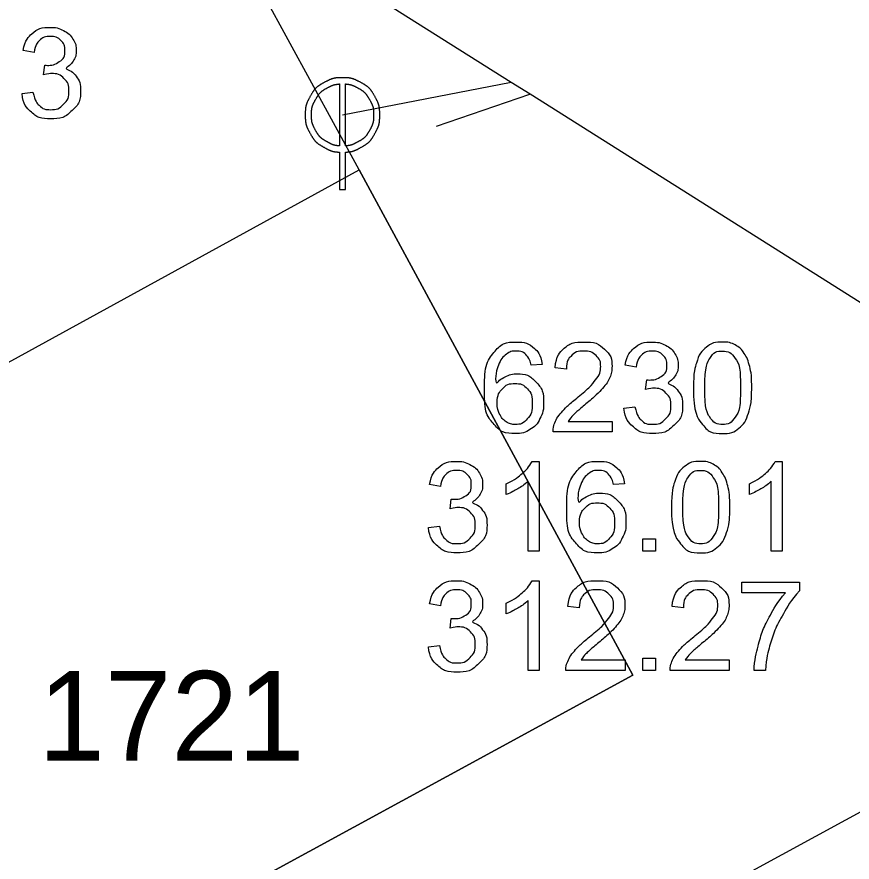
# Model space of a CAD drawing. Extents: x -562248 to -562040, y -1079385 to -1079027.
# Drawn here: x -562106.88 to -562092.87, y -1079267.68 to -1079253.52 of the extents above; entities that cross this region are included whole.
import ezdxf

# ---------------------------------------------------------------- set-up
doc = ezdxf.new("R2010")
doc.units = 0
for name, color, linetype in [('Default', 7, 'Continuous'), ('Kanalizační přípojka', 7, 'Continuous'), ('Kanalizační stoka', 7, 'Continuous'), ('Kanalizační šachta', 7, 'Continuous'), ('Parcela-polygon', 7, 'Continuous'), ('Parcela-text', 7, 'Continuous'), ('Popis šachty', 7, 'Continuous')]:
    doc.layers.add(name, color=color, linetype=linetype)

msp = doc.modelspace()

# ---------------------------------------------------------------- linework, layer by layer
at = {"layer": 'Default'}
for points in [[(-562101.42, -1079254.535), (-562101.526, -1079254.535), (-562101.628, -1079254.562), (-562101.728, -1079254.616)], [(-562101.112, -1079254.616), (-562101.212, -1079254.562), (-562101.314, -1079254.535), (-562101.42, -1079254.535)], [(-562101.728, -1079254.616), (-562101.827, -1079254.669), (-562101.905, -1079254.746), (-562101.961, -1079254.846)], [(-562101.87, -1079254.899), (-562101.824, -1079254.816), (-562101.759, -1079254.751), (-562101.676, -1079254.706)], [(-562101.676, -1079254.706), (-562101.605, -1079254.668), (-562101.536, -1079254.646), (-562101.471, -1079254.64)], [(-562101.369, -1079254.64), (-562101.302, -1079254.646), (-562101.234, -1079254.668), (-562101.164, -1079254.706)], [(-562101.164, -1079254.706), (-562101.081, -1079254.751), (-562101.016, -1079254.816), (-562100.968, -1079254.899)], [(-562100.879, -1079254.846), (-562100.935, -1079254.746), (-562101.013, -1079254.669), (-562101.112, -1079254.616)], [(-562101.961, -1079254.846), (-562102.017, -1079254.946), (-562102.045, -1079255.051), (-562102.045, -1079255.16)], [(-562100.795, -1079255.16), (-562100.795, -1079255.051), (-562100.823, -1079254.946), (-562100.879, -1079254.846)], [(-562101.94, -1079255.16), (-562101.94, -1079255.069), (-562101.917, -1079254.982), (-562101.87, -1079254.899)], [(-562100.968, -1079254.899), (-562100.921, -1079254.982), (-562100.898, -1079255.069), (-562100.898, -1079255.16)], [(-562102.045, -1079255.16), (-562102.045, -1079255.267), (-562102.017, -1079255.371), (-562101.962, -1079255.47)], [(-562101.872, -1079255.418), (-562101.917, -1079255.335), (-562101.94, -1079255.25), (-562101.94, -1079255.16)], [(-562100.898, -1079255.16), (-562100.898, -1079255.25), (-562100.92, -1079255.335), (-562100.966, -1079255.418)], [(-562100.877, -1079255.47), (-562100.822, -1079255.371), (-562100.795, -1079255.267), (-562100.795, -1079255.16)], [(-562101.679, -1079255.609), (-562101.762, -1079255.564), (-562101.826, -1079255.5), (-562101.872, -1079255.418)], [(-562100.966, -1079255.418), (-562101.011, -1079255.5), (-562101.076, -1079255.564), (-562101.159, -1079255.609)], [(-562101.962, -1079255.47), (-562101.907, -1079255.569), (-562101.829, -1079255.647), (-562101.73, -1079255.702)], [(-562101.108, -1079255.702), (-562101.008, -1079255.647), (-562100.931, -1079255.569), (-562100.877, -1079255.47)], [(-562101.73, -1079255.702), (-562101.644, -1079255.751), (-562101.558, -1079255.778), (-562101.471, -1079255.783)], [(-562101.471, -1079255.678), (-562101.54, -1079255.673), (-562101.609, -1079255.65), (-562101.679, -1079255.609)], [(-562101.159, -1079255.609), (-562101.23, -1079255.65), (-562101.3, -1079255.673), (-562101.369, -1079255.678)], [(-562101.369, -1079255.783), (-562101.282, -1079255.778), (-562101.195, -1079255.751), (-562101.108, -1079255.702)]]:
    msp.add_open_spline(points, degree=2, dxfattribs=at)
at = {"layer": 'Kanalizační přípojka'}
for points in [[(-562101.42, -1079255.16), (-562098.59, -1079254.61)], [(-562099.845, -1079255.35), (-562098.28, -1079254.81), (-562098.274, -1079254.808)]]:
    msp.add_lwpolyline(points, dxfattribs=at)
at = {"layer": 'Kanalizační stoka'}
msp.add_lwpolyline([(-562104.57, -1079250.84), (-562098.59, -1079254.61), (-562098.276, -1079254.807), (-562091.1, -1079259.33)], dxfattribs=at)
at = {"layer": 'Kanalizační šachta'}
for points in [[(-562101.471, -1079254.64), (-562101.471, -1079255.678)], [(-562101.369, -1079255.678), (-562101.369, -1079254.64)], [(-562101.471, -1079256.41), (-562101.369, -1079256.41), (-562101.369, -1079255.783)], [(-562101.471, -1079255.783), (-562101.471, -1079256.41)]]:
    msp.add_lwpolyline(points, dxfattribs=at)
at = {"layer": 'Parcela-polygon'}
for points in [[(-562125.839, -1079250.062), (-562115.46, -1079274.84), (-562111.34, -1079272.6), (-562115.82, -1079264.13), (-562111.86, -1079261.96), (-562112.48, -1079260.84), (-562109.81, -1079259.38), (-562109.2, -1079260.5), (-562101.14, -1079256.08), (-562102.73, -1079253.17), (-562100.18, -1079251.98), (-562102.28, -1079247.51), (-562108.03, -1079234.16), (-562113.76, -1079220.84), (-562114.87, -1079218.31), (-562116.77, -1079219.12), (-562123.59, -1079221.97), (-562126.807, -1079223.131)], [(-562092.25, -1079234.14), (-562087.93, -1079243.96), (-562082.03, -1079256.6), (-562081.77, -1079257.15), (-562081.58, -1079257.9), (-562081.53, -1079258.52), (-562081.58, -1079259.09), (-562081.83, -1079259.97), (-562082.29, -1079260.79), (-562083.07, -1079261.58), (-562094.62, -1079267.87), (-562113.94, -1079278.46), (-562115.46, -1079274.84), (-562111.34, -1079272.6), (-562096.55, -1079264.55), (-562101.14, -1079256.08), (-562102.73, -1079253.17), (-562100.18, -1079251.98), (-562102.28, -1079247.51), (-562093.4, -1079243.66), (-562099.13, -1079230.34)], [(-562050.734, -1079242.89), (-562074.7, -1079253.09), (-562082.29, -1079260.79), (-562083.07, -1079261.58), (-562094.62, -1079267.87), (-562113.94, -1079278.46), (-562131.57, -1079288.07), (-562135.96, -1079290.46), (-562143.99, -1079294.84), (-562166.66, -1079307.21), (-562184.27, -1079316.57), (-562201.76, -1079326), (-562209.06, -1079330.03), (-562233.192, -1079343.166)]]:
    msp.add_lwpolyline(points, dxfattribs=at)
msp.add_lwpolyline([(-562112.48, -1079260.84), (-562109.81, -1079259.38), (-562109.2, -1079260.5), (-562101.14, -1079256.08), (-562096.55, -1079264.55), (-562111.34, -1079272.6), (-562115.82, -1079264.13), (-562111.86, -1079261.96)], close=True, dxfattribs=at)
at = {"layer": 'Popis šachty'}
for points in [[(-562106.592, -1079254.114), (-562106.776, -1079254.081)], [(-562106.431, -1079254.487), (-562106.41, -1079254.325)], [(-562106.794, -1079254.8), (-562106.61, -1079254.776)], [(-562098.074, -1079259.341), (-562098.257, -1079259.355)], [(-562097.666, -1079259.419), (-562097.856, -1079259.4)], [(-562096.498, -1079259.389), (-562096.682, -1079259.355)], [(-562096.337, -1079259.761), (-562096.316, -1079259.6)], [(-562096.7, -1079260.075), (-562096.516, -1079260.051)], [(-562096.899, -1079260.295), (-562096.899, -1079260.472), (-562097.89, -1079260.472)], [(-562097.634, -1079260.295), (-562096.899, -1079260.295)], [(-562098.241, -1079260.967), (-562098.123, -1079260.967), (-562098.123, -1079262.472)], [(-562094.164, -1079260.967), (-562094.046, -1079260.967), (-562094.046, -1079262.472)], [(-562099.777, -1079261.389), (-562099.961, -1079261.355)], [(-562098.675, -1079261.521), (-562098.675, -1079261.343)], [(-562098.123, -1079262.472), (-562098.307, -1079262.472), (-562098.307, -1079261.299)], [(-562096.694, -1079261.341), (-562096.877, -1079261.355)], [(-562094.598, -1079261.521), (-562094.598, -1079261.343)], [(-562094.046, -1079262.472), (-562094.23, -1079262.472), (-562094.23, -1079261.299)], [(-562099.616, -1079261.761), (-562099.596, -1079261.6)], [(-562099.979, -1079262.075), (-562099.795, -1079262.051)], [(-562096.383, -1079262.472), (-562096.383, -1079262.263), (-562096.173, -1079262.263), (-562096.173, -1079262.472), (-562096.383, -1079262.472)], [(-562098.241, -1079262.967), (-562098.123, -1079262.967), (-562098.123, -1079264.472)], [(-562094.726, -1079263.169), (-562094.726, -1079262.992), (-562093.755, -1079262.992), (-562093.755, -1079263.135)], [(-562093.992, -1079263.169), (-562094.726, -1079263.169)], [(-562099.777, -1079263.389), (-562099.961, -1079263.355)], [(-562098.675, -1079263.521), (-562098.675, -1079263.343)], [(-562098.123, -1079264.472), (-562098.307, -1079264.472), (-562098.307, -1079263.299)], [(-562097.45, -1079263.419), (-562097.64, -1079263.4)], [(-562095.704, -1079263.419), (-562095.893, -1079263.4)], [(-562099.616, -1079263.761), (-562099.596, -1079263.6)], [(-562099.979, -1079264.075), (-562099.795, -1079264.051)], [(-562096.683, -1079264.295), (-562096.683, -1079264.472), (-562097.675, -1079264.472)], [(-562097.418, -1079264.295), (-562096.683, -1079264.295)], [(-562096.383, -1079264.472), (-562096.383, -1079264.263), (-562096.173, -1079264.263), (-562096.173, -1079264.472), (-562096.383, -1079264.472)], [(-562094.936, -1079264.295), (-562094.936, -1079264.472), (-562095.928, -1079264.472)], [(-562095.672, -1079264.295), (-562094.936, -1079264.295)], [(-562094.327, -1079264.472), (-562094.517, -1079264.472)]]:
    msp.add_lwpolyline(points, dxfattribs=at)
for points in [[(-562106.776, -1079254.081), (-562106.742, -1079253.896), (-562106.622, -1079253.794), (-562106.502, -1079253.692), (-562106.324, -1079253.692), (-562106.201, -1079253.692), (-562106.098, -1079253.745), (-562105.995, -1079253.797), (-562105.94, -1079253.888), (-562105.885, -1079253.979), (-562105.885, -1079254.081), (-562105.885, -1079254.178), (-562105.937, -1079254.258), (-562105.989, -1079254.338), (-562106.092, -1079254.385), (-562105.959, -1079254.415), (-562105.885, -1079254.512), (-562105.812, -1079254.609), (-562105.812, -1079254.754), (-562105.812, -1079254.95), (-562105.955, -1079255.086), (-562106.098, -1079255.223), (-562106.317, -1079255.223), (-562106.515, -1079255.223), (-562106.645, -1079255.105), (-562106.776, -1079254.987), (-562106.794, -1079254.8)], [(-562106.41, -1079254.325), (-562106.392, -1079254.328), (-562106.381, -1079254.328), (-562106.263, -1079254.328), (-562106.169, -1079254.266), (-562106.075, -1079254.205), (-562106.075, -1079254.077), (-562106.075, -1079253.976), (-562106.143, -1079253.909), (-562106.212, -1079253.843), (-562106.32, -1079253.843), (-562106.428, -1079253.843), (-562106.499, -1079253.911), (-562106.571, -1079253.978), (-562106.592, -1079254.114)], [(-562106.61, -1079254.776), (-562106.578, -1079254.933), (-562106.502, -1079255.002), (-562106.426, -1079255.071), (-562106.316, -1079255.071), (-562106.186, -1079255.071), (-562106.097, -1079254.981), (-562106.007, -1079254.891), (-562106.007, -1079254.758), (-562106.007, -1079254.631), (-562106.09, -1079254.549), (-562106.173, -1079254.466), (-562106.301, -1079254.466), (-562106.353, -1079254.466), (-562106.431, -1079254.487)], [(-562098.257, -1079259.355), (-562098.282, -1079259.246), (-562098.327, -1079259.197), (-562098.402, -1079259.118), (-562098.512, -1079259.118), (-562098.6, -1079259.118), (-562098.667, -1079259.167), (-562098.754, -1079259.23), (-562098.804, -1079259.352), (-562098.854, -1079259.474), (-562098.856, -1079259.699), (-562098.79, -1079259.598), (-562098.693, -1079259.549), (-562098.597, -1079259.499), (-562098.492, -1079259.499), (-562098.307, -1079259.499), (-562098.178, -1079259.635), (-562098.048, -1079259.77), (-562098.048, -1079259.985), (-562098.048, -1079260.126), (-562098.109, -1079260.248), (-562098.17, -1079260.369), (-562098.276, -1079260.433), (-562098.383, -1079260.498), (-562098.518, -1079260.498), (-562098.748, -1079260.498), (-562098.894, -1079260.328), (-562099.039, -1079260.159), (-562099.039, -1079259.77), (-562099.039, -1079259.336), (-562098.878, -1079259.138), (-562098.738, -1079258.967), (-562098.5, -1079258.967), (-562098.323, -1079258.967), (-562098.21, -1079259.066), (-562098.097, -1079259.165), (-562098.074, -1079259.341)], [(-562097.856, -1079259.4), (-562097.836, -1079259.188), (-562097.71, -1079259.078), (-562097.583, -1079258.967), (-562097.369, -1079258.967), (-562097.153, -1079258.967), (-562097.027, -1079259.086), (-562096.901, -1079259.206), (-562096.901, -1079259.383), (-562096.901, -1079259.473), (-562096.938, -1079259.56), (-562096.975, -1079259.647), (-562097.06, -1079259.743), (-562097.145, -1079259.839), (-562097.344, -1079260.007), (-562097.509, -1079260.146), (-562097.556, -1079260.195), (-562097.603, -1079260.245), (-562097.634, -1079260.295)], [(-562096.682, -1079259.355), (-562096.648, -1079259.17), (-562096.528, -1079259.068), (-562096.408, -1079258.967), (-562096.23, -1079258.967), (-562096.107, -1079258.967), (-562096.004, -1079259.019), (-562095.901, -1079259.072), (-562095.846, -1079259.163), (-562095.791, -1079259.254), (-562095.791, -1079259.356), (-562095.791, -1079259.453), (-562095.843, -1079259.533), (-562095.895, -1079259.612), (-562095.998, -1079259.659), (-562095.865, -1079259.69), (-562095.791, -1079259.787), (-562095.718, -1079259.883), (-562095.718, -1079260.028), (-562095.718, -1079260.225), (-562095.861, -1079260.361), (-562096.004, -1079260.498), (-562096.223, -1079260.498), (-562096.421, -1079260.498), (-562096.551, -1079260.38), (-562096.682, -1079260.262), (-562096.7, -1079260.075)], [(-562095.536, -1079259.733), (-562095.536, -1079259.467), (-562095.481, -1079259.304), (-562095.427, -1079259.142), (-562095.319, -1079259.054), (-562095.211, -1079258.967), (-562095.047, -1079258.967), (-562094.927, -1079258.967), (-562094.835, -1079259.015), (-562094.744, -1079259.064), (-562094.685, -1079259.155), (-562094.626, -1079259.247), (-562094.592, -1079259.378), (-562094.559, -1079259.51), (-562094.559, -1079259.733), (-562094.559, -1079259.996), (-562094.613, -1079260.159), (-562094.667, -1079260.321), (-562094.775, -1079260.409), (-562094.883, -1079260.498), (-562095.047, -1079260.498), (-562095.264, -1079260.498), (-562095.388, -1079260.343), (-562095.536, -1079260.155), (-562095.536, -1079259.733)], [(-562097.89, -1079260.472), (-562097.892, -1079260.406), (-562097.869, -1079260.344), (-562097.831, -1079260.243), (-562097.747, -1079260.145), (-562097.664, -1079260.047), (-562097.506, -1079259.918), (-562097.262, -1079259.717), (-562097.177, -1079259.6), (-562097.091, -1079259.483), (-562097.091, -1079259.378), (-562097.091, -1079259.269), (-562097.169, -1079259.194), (-562097.247, -1079259.119), (-562097.373, -1079259.119), (-562097.506, -1079259.119), (-562097.585, -1079259.199), (-562097.665, -1079259.278), (-562097.666, -1079259.419)], [(-562096.316, -1079259.6), (-562096.298, -1079259.602), (-562096.287, -1079259.602), (-562096.169, -1079259.602), (-562096.075, -1079259.541), (-562095.981, -1079259.479), (-562095.981, -1079259.352), (-562095.981, -1079259.25), (-562096.049, -1079259.184), (-562096.118, -1079259.118), (-562096.226, -1079259.118), (-562096.334, -1079259.118), (-562096.406, -1079259.185), (-562096.477, -1079259.253), (-562096.498, -1079259.389)], [(-562095.346, -1079259.733), (-562095.346, -1079260.103), (-562095.26, -1079260.225), (-562095.174, -1079260.347), (-562095.047, -1079260.347), (-562094.921, -1079260.347), (-562094.835, -1079260.224), (-562094.748, -1079260.102), (-562094.748, -1079259.733), (-562094.748, -1079259.362), (-562094.834, -1079259.241), (-562094.921, -1079259.119), (-562095.049, -1079259.119), (-562095.176, -1079259.119), (-562095.252, -1079259.226), (-562095.346, -1079259.363), (-562095.346, -1079259.733)], [(-562098.828, -1079259.986), (-562098.828, -1079260.082), (-562098.787, -1079260.169), (-562098.747, -1079260.256), (-562098.675, -1079260.301), (-562098.602, -1079260.347), (-562098.522, -1079260.347), (-562098.405, -1079260.347), (-562098.321, -1079260.252), (-562098.238, -1079260.158), (-562098.238, -1079259.997), (-562098.238, -1079259.841), (-562098.32, -1079259.751), (-562098.403, -1079259.662), (-562098.529, -1079259.662), (-562098.654, -1079259.662), (-562098.741, -1079259.751), (-562098.828, -1079259.841), (-562098.828, -1079259.986)], [(-562096.516, -1079260.051), (-562096.484, -1079260.207), (-562096.408, -1079260.276), (-562096.332, -1079260.345), (-562096.222, -1079260.345), (-562096.092, -1079260.345), (-562096.003, -1079260.255), (-562095.913, -1079260.165), (-562095.913, -1079260.032), (-562095.913, -1079259.906), (-562095.996, -1079259.823), (-562096.079, -1079259.741), (-562096.207, -1079259.741), (-562096.259, -1079259.741), (-562096.337, -1079259.761)], [(-562099.961, -1079261.355), (-562099.927, -1079261.17), (-562099.808, -1079261.068), (-562099.688, -1079260.967), (-562099.51, -1079260.967), (-562099.387, -1079260.967), (-562099.283, -1079261.019), (-562099.18, -1079261.072), (-562099.125, -1079261.163), (-562099.071, -1079261.254), (-562099.071, -1079261.356), (-562099.071, -1079261.453), (-562099.123, -1079261.533), (-562099.175, -1079261.612), (-562099.277, -1079261.659), (-562099.144, -1079261.69), (-562099.071, -1079261.787), (-562098.997, -1079261.883), (-562098.997, -1079262.028), (-562098.997, -1079262.225), (-562099.141, -1079262.361), (-562099.284, -1079262.498), (-562099.503, -1079262.498), (-562099.7, -1079262.498), (-562099.831, -1079262.38), (-562099.961, -1079262.262), (-562099.979, -1079262.075)], [(-562098.675, -1079261.343), (-562098.521, -1079261.27), (-562098.405, -1079261.167), (-562098.289, -1079261.064), (-562098.241, -1079260.967)], [(-562096.877, -1079261.355), (-562096.901, -1079261.246), (-562096.946, -1079261.197), (-562097.021, -1079261.118), (-562097.131, -1079261.118), (-562097.219, -1079261.118), (-562097.286, -1079261.167), (-562097.373, -1079261.23), (-562097.423, -1079261.352), (-562097.474, -1079261.474), (-562097.476, -1079261.699), (-562097.409, -1079261.598), (-562097.313, -1079261.549), (-562097.216, -1079261.499), (-562097.111, -1079261.499), (-562096.926, -1079261.499), (-562096.797, -1079261.635), (-562096.667, -1079261.77), (-562096.667, -1079261.985), (-562096.667, -1079262.126), (-562096.728, -1079262.248), (-562096.789, -1079262.369), (-562096.896, -1079262.433), (-562097.002, -1079262.498), (-562097.137, -1079262.498), (-562097.368, -1079262.498), (-562097.513, -1079262.328), (-562097.659, -1079262.159), (-562097.659, -1079261.77), (-562097.659, -1079261.336), (-562097.498, -1079261.138), (-562097.357, -1079260.967), (-562097.12, -1079260.967), (-562096.943, -1079260.967), (-562096.829, -1079261.066), (-562096.716, -1079261.165), (-562096.694, -1079261.341)], [(-562095.904, -1079261.733), (-562095.904, -1079261.467), (-562095.849, -1079261.304), (-562095.794, -1079261.142), (-562095.686, -1079261.054), (-562095.578, -1079260.967), (-562095.415, -1079260.967), (-562095.294, -1079260.967), (-562095.203, -1079261.015), (-562095.112, -1079261.064), (-562095.053, -1079261.155), (-562094.994, -1079261.247), (-562094.96, -1079261.378), (-562094.926, -1079261.51), (-562094.926, -1079261.733), (-562094.926, -1079261.996), (-562094.98, -1079262.159), (-562095.034, -1079262.321), (-562095.142, -1079262.409), (-562095.25, -1079262.498), (-562095.415, -1079262.498), (-562095.632, -1079262.498), (-562095.755, -1079262.343), (-562095.904, -1079262.155), (-562095.904, -1079261.733)], [(-562094.598, -1079261.343), (-562094.444, -1079261.27), (-562094.328, -1079261.167), (-562094.212, -1079261.064), (-562094.164, -1079260.967)], [(-562099.596, -1079261.6), (-562099.577, -1079261.602), (-562099.566, -1079261.602), (-562099.449, -1079261.602), (-562099.354, -1079261.541), (-562099.26, -1079261.479), (-562099.26, -1079261.352), (-562099.26, -1079261.25), (-562099.329, -1079261.184), (-562099.397, -1079261.118), (-562099.506, -1079261.118), (-562099.613, -1079261.118), (-562099.685, -1079261.185), (-562099.757, -1079261.253), (-562099.777, -1079261.389)], [(-562095.714, -1079261.733), (-562095.714, -1079262.103), (-562095.628, -1079262.225), (-562095.541, -1079262.347), (-562095.415, -1079262.347), (-562095.288, -1079262.347), (-562095.202, -1079262.224), (-562095.116, -1079262.102), (-562095.116, -1079261.733), (-562095.116, -1079261.362), (-562095.202, -1079261.241), (-562095.288, -1079261.119), (-562095.417, -1079261.119), (-562095.543, -1079261.119), (-562095.619, -1079261.226), (-562095.714, -1079261.363), (-562095.714, -1079261.733)], [(-562098.307, -1079261.299), (-562098.373, -1079261.363), (-562098.481, -1079261.426), (-562098.589, -1079261.489), (-562098.675, -1079261.521)], [(-562094.23, -1079261.299), (-562094.296, -1079261.363), (-562094.404, -1079261.426), (-562094.512, -1079261.489), (-562094.598, -1079261.521)], [(-562097.447, -1079261.986), (-562097.447, -1079262.082), (-562097.407, -1079262.169), (-562097.366, -1079262.256), (-562097.294, -1079262.301), (-562097.222, -1079262.347), (-562097.141, -1079262.347), (-562097.024, -1079262.347), (-562096.941, -1079262.252), (-562096.857, -1079262.158), (-562096.857, -1079261.997), (-562096.857, -1079261.841), (-562096.94, -1079261.751), (-562097.022, -1079261.662), (-562097.148, -1079261.662), (-562097.273, -1079261.662), (-562097.36, -1079261.751), (-562097.447, -1079261.841), (-562097.447, -1079261.986)], [(-562099.795, -1079262.051), (-562099.764, -1079262.207), (-562099.688, -1079262.276), (-562099.612, -1079262.345), (-562099.502, -1079262.345), (-562099.371, -1079262.345), (-562099.282, -1079262.255), (-562099.193, -1079262.165), (-562099.193, -1079262.032), (-562099.193, -1079261.906), (-562099.276, -1079261.823), (-562099.359, -1079261.741), (-562099.486, -1079261.741), (-562099.539, -1079261.741), (-562099.616, -1079261.761)], [(-562099.961, -1079263.355), (-562099.927, -1079263.17), (-562099.808, -1079263.068), (-562099.688, -1079262.967), (-562099.51, -1079262.967), (-562099.387, -1079262.967), (-562099.283, -1079263.019), (-562099.18, -1079263.072), (-562099.125, -1079263.163), (-562099.071, -1079263.254), (-562099.071, -1079263.356), (-562099.071, -1079263.453), (-562099.123, -1079263.533), (-562099.175, -1079263.612), (-562099.277, -1079263.659), (-562099.144, -1079263.69), (-562099.071, -1079263.787), (-562098.997, -1079263.883), (-562098.997, -1079264.028), (-562098.997, -1079264.225), (-562099.141, -1079264.361), (-562099.284, -1079264.498), (-562099.503, -1079264.498), (-562099.7, -1079264.498), (-562099.831, -1079264.38), (-562099.961, -1079264.262), (-562099.979, -1079264.075)], [(-562098.675, -1079263.343), (-562098.521, -1079263.27), (-562098.405, -1079263.167), (-562098.289, -1079263.064), (-562098.241, -1079262.967)], [(-562097.64, -1079263.4), (-562097.621, -1079263.188), (-562097.494, -1079263.078), (-562097.367, -1079262.967), (-562097.153, -1079262.967), (-562096.937, -1079262.967), (-562096.811, -1079263.086), (-562096.686, -1079263.206), (-562096.686, -1079263.383), (-562096.686, -1079263.473), (-562096.722, -1079263.56), (-562096.759, -1079263.647), (-562096.845, -1079263.743), (-562096.93, -1079263.839), (-562097.128, -1079264.007), (-562097.294, -1079264.146), (-562097.341, -1079264.195), (-562097.388, -1079264.245), (-562097.418, -1079264.295)], [(-562095.893, -1079263.4), (-562095.874, -1079263.188), (-562095.747, -1079263.078), (-562095.62, -1079262.967), (-562095.406, -1079262.967), (-562095.19, -1079262.967), (-562095.064, -1079263.086), (-562094.939, -1079263.206), (-562094.939, -1079263.383), (-562094.939, -1079263.473), (-562094.975, -1079263.56), (-562095.012, -1079263.647), (-562095.098, -1079263.743), (-562095.183, -1079263.839), (-562095.381, -1079264.007), (-562095.547, -1079264.146), (-562095.594, -1079264.195), (-562095.641, -1079264.245), (-562095.672, -1079264.295)], [(-562099.596, -1079263.6), (-562099.577, -1079263.602), (-562099.566, -1079263.602), (-562099.449, -1079263.602), (-562099.354, -1079263.541), (-562099.26, -1079263.479), (-562099.26, -1079263.352), (-562099.26, -1079263.25), (-562099.329, -1079263.184), (-562099.397, -1079263.118), (-562099.506, -1079263.118), (-562099.613, -1079263.118), (-562099.685, -1079263.185), (-562099.757, -1079263.253), (-562099.777, -1079263.389)], [(-562097.675, -1079264.472), (-562097.677, -1079264.406), (-562097.653, -1079264.344), (-562097.615, -1079264.243), (-562097.532, -1079264.145), (-562097.448, -1079264.047), (-562097.291, -1079263.918), (-562097.047, -1079263.717), (-562096.961, -1079263.6), (-562096.875, -1079263.483), (-562096.875, -1079263.378), (-562096.875, -1079263.269), (-562096.954, -1079263.194), (-562097.032, -1079263.119), (-562097.157, -1079263.119), (-562097.29, -1079263.119), (-562097.37, -1079263.199), (-562097.449, -1079263.278), (-562097.45, -1079263.419)], [(-562095.928, -1079264.472), (-562095.93, -1079264.406), (-562095.906, -1079264.344), (-562095.868, -1079264.243), (-562095.785, -1079264.145), (-562095.701, -1079264.047), (-562095.544, -1079263.918), (-562095.3, -1079263.717), (-562095.214, -1079263.6), (-562095.128, -1079263.483), (-562095.128, -1079263.378), (-562095.128, -1079263.269), (-562095.207, -1079263.194), (-562095.285, -1079263.119), (-562095.41, -1079263.119), (-562095.543, -1079263.119), (-562095.623, -1079263.199), (-562095.702, -1079263.278), (-562095.704, -1079263.419)], [(-562094.517, -1079264.472), (-562094.514, -1079264.295), (-562094.447, -1079264.045), (-562094.381, -1079263.794), (-562094.256, -1079263.561), (-562094.132, -1079263.329), (-562093.992, -1079263.169)], [(-562093.755, -1079263.135), (-562093.898, -1079263.288), (-562094.039, -1079263.54), (-562094.18, -1079263.793), (-562094.256, -1079264.06), (-562094.312, -1079264.248), (-562094.327, -1079264.472)], [(-562098.307, -1079263.299), (-562098.373, -1079263.363), (-562098.481, -1079263.426), (-562098.589, -1079263.489), (-562098.675, -1079263.521)], [(-562099.795, -1079264.051), (-562099.764, -1079264.207), (-562099.688, -1079264.276), (-562099.612, -1079264.345), (-562099.502, -1079264.345), (-562099.371, -1079264.345), (-562099.282, -1079264.255), (-562099.193, -1079264.165), (-562099.193, -1079264.032), (-562099.193, -1079263.906), (-562099.276, -1079263.823), (-562099.359, -1079263.741), (-562099.486, -1079263.741), (-562099.539, -1079263.741), (-562099.616, -1079263.761)]]:
    msp.add_open_spline(points, degree=3, dxfattribs=at)

# ---------------------------------------------------------------- texts
at = {"layer": 'Parcela-text'}
msp.add_text('1721', height=1.5, dxfattribs=at).set_placement((-562106.52, -1079265.98))

doc.saveas('drawing.dxf')
